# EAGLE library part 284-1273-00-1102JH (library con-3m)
Zero Insertion Force Socked Source: http://www.3M.com/ehpd
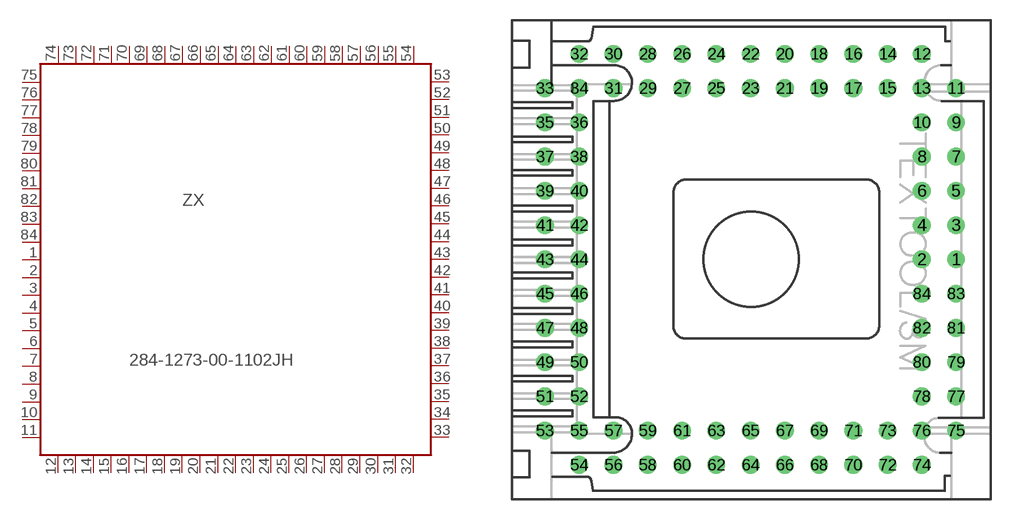
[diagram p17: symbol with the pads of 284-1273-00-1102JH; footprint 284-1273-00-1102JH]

Designator prefix ZX

## 284-1273-00-1102JH (OC_FARNELL: unknown; OC_NEWARK: unknown)  [284-1273-00-1102JH]
1  1  pas
2  2  pas
3  3  pas
4  4  pas
5  5  pas
6  6  pas
7  7  pas
8  8  pas
9  9  pas
10  10  pas
11  11  pas
12  12  pas
13  13  pas
14  14  pas
15  15  pas
16  16  pas
17  17  pas
18  18  pas
19  19  pas
20  20  pas
21  21  pas
22  22  pas
23  23  pas
24  24  pas
25  25  pas
26  26  pas
27  27  pas
28  28  pas
29  29  pas
30  30  pas
31  31  pas
32  32  pas
33  33  pas
34  34  pas
35  35  pas
36  36  pas
37  37  pas
38  38  pas
39  39  pas
40  40  pas
41  41  pas
42  42  pas
43  43  pas
44  44  pas
45  45  pas
46  46  pas
47  47  pas
48  48  pas
49  49  pas
50  50  pas
51  51  pas
52  52  pas
53  53  pas
54  54  pas
55  55  pas
56  56  pas
57  57  pas
58  58  pas
59  59  pas
60  60  pas
61  61  pas
62  62  pas
63  63  pas
64  64  pas
65  65  pas
66  66  pas
67  67  pas
68  68  pas
69  69  pas
70  70  pas
71  71  pas
72  72  pas
73  73  pas
74  74  pas
75  75  pas
76  76  pas
77  77  pas
78  78  pas
79  79  pas
80  80  pas
81  81  pas
82  82  pas
83  83  pas
84  84  pas

## Footprint 284-1273-00-1102JH (pad centres in mm)
OEM LCC Sockets 84 pol. Source: http://www.3M.com/ehpd
drill 0.8 pad 1.27 round: 1 15.24,0; 2 12.7,0; 3 15.24,2.54; 4 12.7,2.54; 5 15.24,5.08; 6 12.7,5.08; 7 15.24,7.62; 8 12.7,7.62; 9 15.24,10.16; 10 12.7,10.16; 11 15.24,12.7; 12 12.7,15.24; 13 12.7,12.7; 14 10.16,15.24; 15 10.16,12.7; 16 7.62,15.24; 17 7.62,12.7; 18 5.08,15.24; 19 5.08,12.7; 20 2.54,15.24; 21 2.54,12.7; 22 0,15.24; 23 0,12.7; 24 -2.54,15.24; 25 -2.54,12.7; 26 -5.08,15.24; 27 -5.08,12.7; 28 -7.62,15.24; 29 -7.62,12.7; 30 -10.16,15.24; 31 -10.16,12.7; 32 -12.7,15.24; 33 -15.24,12.7; 34 -12.7,12.7; 35 -15.24,10.16; 36 -12.7,10.16; 37 -15.24,7.62; 38 -12.7,7.62; 39 -15.24,5.08; 40 -12.7,5.08; 41 -15.24,2.54; 42 -12.7,2.54; 43 -15.24,0; 44 -12.7,0; 45 -15.24,-2.54; 46 -12.7,-2.54; 47 -15.24,-5.08; 48 -12.7,-5.08; 49 -15.24,-7.62; 50 -12.7,-7.62; 51 -15.24,-10.16; 52 -12.7,-10.16; 53 -15.24,-12.7; 54 -12.7,-15.24; 55 -12.7,-12.7; 56 -10.16,-15.24; 57 -10.16,-12.7; 58 -7.62,-15.24; 59 -7.62,-12.7; 60 -5.08,-15.24; 61 -5.08,-12.7; 62 -2.54,-15.24; 63 -2.54,-12.7; 64 0,-15.24; 65 0,-12.7; 66 2.54,-15.24; 67 2.54,-12.7; 68 5.08,-15.24; 69 5.08,-12.7; 70 7.62,-15.24; 71 7.62,-12.7; 72 10.16,-15.24; 73 10.16,-12.7; 74 12.7,-15.24; 75 15.24,-12.7; 76 12.7,-12.7; 77 15.24,-10.16; 78 12.7,-10.16; 79 15.24,-7.62; 80 12.7,-7.62; 81 15.24,-5.08; 82 12.7,-5.08; 83 15.24,-2.54; 84 12.7,-2.54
